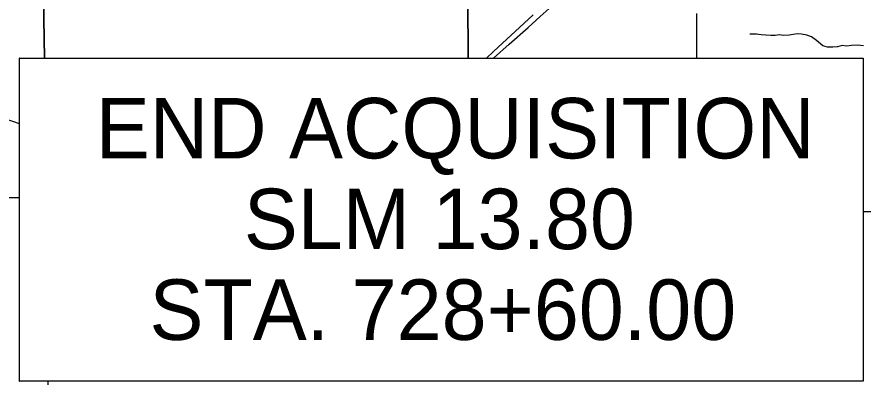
# Model space of a CAD drawing. Extents: x 0 to 34, y 0 to 22.
# Drawn here: x 4.028 to 5.987, y 17.462 to 18.295 of the extents above; entities that cross this region are included whole.
import ezdxf

# ---------------------------------------------------------------- set-up
doc = ezdxf.new("R2010")
doc.units = 0
for name, color, linetype in [('Default', 7, 'Continuous'), ('GM_X_Minor_River', 7, 'Continuous'), ('GM_X_Section', 7, 'Continuous'), ('GM_X_State_Route', 7, 'Continuous'), ('GM_X_Township_Road', 7, 'Continuous'), ('GM_X_US_Route', 7, 'Continuous'), ('SH_Text', 7, 'Continuous')]:
    doc.layers.add(name, color=color, linetype=linetype)

msp = doc.modelspace()

# ---------------------------------------------------------------- linework, layer by layer
at = {"layer": 'Default'}
for points in [[(4.0336, 17.4527), (4.0336, 18.2003), (4.0332, 18.2003), (4.0332, 17.4527)], [(4.0336, 18.2003), (5.9872, 18.2003), (5.9872, 17.4527), (4.0336, 17.4527)]]:
    msp.add_lwpolyline(points, close=True, dxfattribs=at)
at = {"layer": 'GM_X_Minor_River'}
msp.add_lwpolyline([(5.9877, 18.2287), (5.9737, 18.2303), (5.9601, 18.2293), (5.9487, 18.2279), (5.9381, 18.2292), (5.9275, 18.2262), (5.9165, 18.2252), (5.9044, 18.2253), (5.8938, 18.2288), (5.8791, 18.2407), (5.8675, 18.2496), (5.8565, 18.2535), (5.8444, 18.2555), (5.8346, 18.2567), (5.8251, 18.2545), (5.8156, 18.2531), (5.8035, 18.2525), (5.7929, 18.2541), (5.7834, 18.2527), (5.7732, 18.2528), (5.7615, 18.2536), (5.7512, 18.2541), (5.7399, 18.2554), (5.7274, 18.2559), (5.7244, 18.2555)], dxfattribs=at)
at = {"layer": 'GM_X_Section'}
for points in [[(4.0919, 18.2003), (4.08, 18.8834), (3.073, 18.8909), (3.0924, 17.8824), (4.0336, 17.8765), (4.0336, 18.2003)], [(5.0723, 18.2003), (5.0689, 18.882), (4.08, 18.8834), (4.0919, 18.2003)], [(5.9868, 17.8455), (6.1027, 17.8448), (6.0998, 18.8817), (5.0689, 18.882), (5.0723, 18.2003), (5.9868, 18.2003)], [(4.0336, 17.8765), (3.0924, 17.8824), (3.1023, 16.8785), (3.2153, 16.8759), (4.1045, 16.8706), (4.1005, 17.4527), (4.0336, 17.4527)]]:
    msp.add_lwpolyline(points, close=True, dxfattribs=at)
at = {"layer": 'GM_X_State_Route'}
msp.add_lwpolyline([(4.0336, 18.0477), (4.0003, 18.0599)], dxfattribs=at)
at = {"layer": 'GM_X_Township_Road'}
msp.add_lwpolyline([(5.6021, 18.2003), (5.6021, 18.202), (5.6022, 18.2265), (5.6021, 18.2423), (5.6021, 18.2557), (5.602, 18.2702), (5.6021, 18.2911), (5.6017, 18.3037)], dxfattribs=at)
at = {"layer": 'GM_X_US_Route'}
for points in [[(5.1315, 18.2003), (5.1675, 18.2322), (5.2116, 18.2714), (5.2394, 18.2963), (5.2811, 18.3336), (5.3509, 18.3955), (5.3922, 18.4332), (5.4283, 18.4661), (5.4382, 18.475), (5.4887, 18.521), (5.5324, 18.5608), (5.6126, 18.6343), (5.6402, 18.6593), (5.6768, 18.693), (5.7181, 18.7307), (5.7526, 18.7621), (5.7894, 18.7955), (5.8329, 18.8356), (5.8769, 18.8749), (5.9115, 18.9061), (5.9485, 18.9394), (5.9852, 18.9729), (6.0248, 19.0079)], [(5.1147, 18.2003), (5.1315, 18.2158), (5.2021, 18.2813), (5.2228, 18.3001)]]:
    msp.add_lwpolyline(points, dxfattribs=at)
at = {"layer": 'SH_Text'}
msp.add_lwpolyline([(4.0336, 18.2003), (5.9868, 18.2003), (5.9868, 17.4527), (4.0336, 17.4527)], close=True, dxfattribs=at)

# ---------------------------------------------------------------- texts
at = {"layer": 'Default'}
for s, p in [('END ACQUISITION', (4.2105, 17.968)), ('SLM 13.80', (4.5532, 17.758)), ('STA. 728+60.00', (4.3347, 17.548))]:
    msp.add_text(s, height=0.14, dxfattribs=at).set_placement(p)

doc.saveas('drawing.dxf')
